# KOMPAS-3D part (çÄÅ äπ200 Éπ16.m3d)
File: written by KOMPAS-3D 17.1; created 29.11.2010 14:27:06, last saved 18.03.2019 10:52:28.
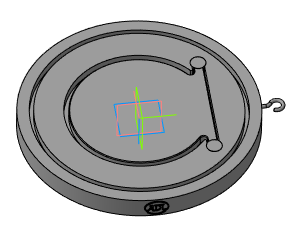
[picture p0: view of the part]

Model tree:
1. Плоскость XY
2. Плоскость ZX
3. Плоскость ZY
4. Ось X
5. Ось Y
6. Ось Z
7. Начало координат
8. Операция без истории:2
